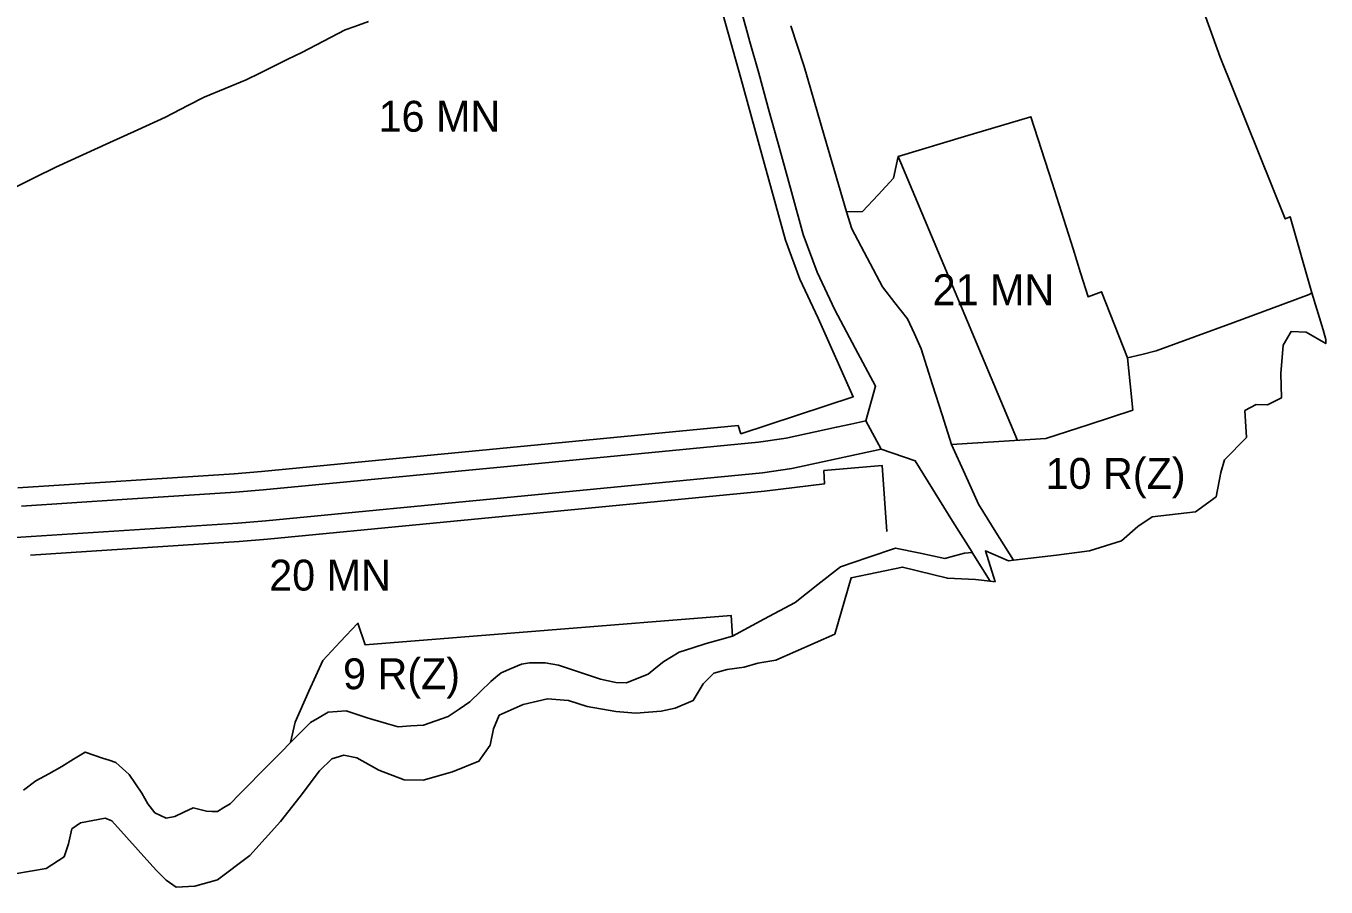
# Model space of a CAD drawing. Extents: x -294445 to -292055, y 21869 to 23693.
# Drawn here: x -292476 to -292055.2, y 22319.6 to 22598.3 of the extents above; entities that cross this region are included whole.
import ezdxf

# ---------------------------------------------------------------- set-up
doc = ezdxf.new("R2010")
doc.units = 0
for name, color, linetype in [('linie_rozgraniczajace', 7, 'Continuous'), ('linie_zabudowy_nieprzekraczalne', 7, 'Continuous'), ('oznaczenia_przeznaczen', 7, 'Continuous')]:
    doc.layers.add(name, color=color, linetype=linetype)

msp = doc.modelspace()

# ---------------------------------------------------------------- linework, layer by layer
at = {"layer": 'linie_rozgraniczajace'}
for points in [[(-292096.57, 22608.04), (-292089.46, 22588.21), (-292068.43, 22535.88), (-292066.8, 22536.58), (-292059.86, 22511.98), (-292060.63, 22511.36), (-292069.128, 22508.23), (-292085.395, 22502.24), (-292110.16, 22493.12), (-292114.84, 22492.01), (-292119.52, 22490.9), (-292123.697, 22501.579), (-292127.875, 22512.259), (-292132.232, 22510.64), (-292134.648, 22518.391), (-292137.063, 22526.143), (-292143.896, 22547.532), (-292150.728, 22568.92), (-292172.208, 22562.503), (-292193.688, 22556.086), (-292195.255, 22549.031), (-292200.228, 22543.666), (-292205.2, 22538.3), (-292210.442, 22538.143), (-292217.625, 22562.805), (-292224.1, 22585.18), (-292228.45, 22598.345)], [(-292244.54, 22603.42), (-292241.69, 22593.21), (-292238.84, 22583), (-292235.435, 22570.67), (-292232.03, 22558.34), (-292228.234, 22544.575), (-292224.439, 22530.811), (-292219.969, 22518.66), (-292214.193, 22506.428), (-292207.612, 22494.063), (-292201.031, 22481.699), (-292204.133, 22470.5), (-292208.978, 22469.445), (-292213.636, 22468.432), (-292229.918, 22464.929), (-292238.876, 22463.599), (-292319.059, 22455.861), (-292399.242, 22448.123), (-292408.21, 22447.394), (-292444.844, 22445.015), (-292477.478, 22442.897)], [(-292228.45, 22598.345), (-292224.1, 22585.18), (-292217.625, 22562.805), (-292210.442, 22538.143), (-292208.74, 22532.64), (-292203.76, 22523.245), (-292198.78, 22513.85), (-292194.745, 22508.675), (-292190.71, 22503.5), (-292188.465, 22498.66), (-292186.22, 22493.82), (-292184.38, 22488.005), (-292182.54, 22482.19), (-292179.47, 22472.495), (-292176.405, 22462.814), (-292172.039, 22453.155), (-292167.677, 22443.511), (-292162.04, 22434.443), (-292156.402, 22425.375), (-292158.03, 22425.18), (-292165.49, 22428.42), (-292162.36, 22418.41), (-292163.963, 22418.597), (-292169.771, 22427.938), (-292169.772, 22427.94), (-292176.066, 22438.065), (-292188.17, 22457.533), (-292199.252, 22461.328), (-292204.133, 22470.5), (-292201.031, 22481.699), (-292207.612, 22494.063), (-292214.193, 22506.428), (-292219.969, 22518.66), (-292224.439, 22530.811), (-292228.234, 22544.575), (-292232.03, 22558.34), (-292235.435, 22570.67), (-292238.84, 22583), (-292241.69, 22593.21), (-292244.54, 22603.42)], [(-292479.86, 22545.93), (-292473.11, 22549.255), (-292466.36, 22552.58), (-292457.6, 22556.565), (-292448.84, 22560.55), (-292439.771, 22564.687), (-292430.8, 22568.78), (-292423.579, 22572.535), (-292418.3, 22575.28), (-292411.525, 22578.075), (-292404.75, 22580.87), (-292400.265, 22583.08), (-292395.78, 22585.29), (-292391.27, 22587.51), (-292386.76, 22589.73), (-292379.72, 22593.38), (-292372.68, 22597.03), (-292369.55, 22598.15), (-292365.19, 22599.78)], [(-292365.19, 22599.78), (-292369.55, 22598.15), (-292372.68, 22597.03), (-292379.72, 22593.38), (-292386.76, 22589.73), (-292391.27, 22587.51), (-292395.78, 22585.29), (-292400.265, 22583.08), (-292404.75, 22580.87), (-292411.525, 22578.075), (-292418.3, 22575.28), (-292423.579, 22572.535), (-292430.8, 22568.78), (-292439.771, 22564.687), (-292448.84, 22560.55), (-292457.6, 22556.565), (-292466.36, 22552.58), (-292473.11, 22549.255)], [(-292473.11, 22549.255), (-292479.86, 22545.93)], [(-292477.478, 22442.897), (-292444.844, 22445.015), (-292408.21, 22447.394), (-292399.242, 22448.123), (-292319.059, 22455.861), (-292238.876, 22463.599), (-292229.918, 22464.929), (-292213.636, 22468.432), (-292208.978, 22469.445), (-292204.133, 22470.5), (-292199.252, 22461.328), (-292228.146, 22455.082), (-292237.661, 22453.67), (-292318.009, 22445.916), (-292398.356, 22438.162), (-292407.48, 22437.42), (-292444.252, 22435.03), (-292481.025, 22432.64)], [(-292481.025, 22432.64), (-292444.252, 22435.03), (-292407.48, 22437.42), (-292398.356, 22438.162), (-292318.009, 22445.916), (-292237.661, 22453.67), (-292228.146, 22455.082), (-292199.252, 22461.328), (-292188.17, 22457.533), (-292176.066, 22438.065), (-292169.772, 22427.94), (-292169.771, 22427.938), (-292172.27, 22427.66), (-292175.46, 22426.82), (-292178.65, 22425.98), (-292186.63, 22427.66), (-292194.61, 22429.34), (-292203.51, 22426.3), (-292212.41, 22423.26), (-292219.75, 22417.5), (-292227.09, 22411.74), (-292237.225, 22406.285), (-292247.36, 22400.83), (-292247.714, 22407.453), (-292306.977, 22402.747), (-292366.24, 22398.04), (-292368.58, 22405.01), (-292374.26, 22398.985), (-292379.94, 22392.96), (-292384.415, 22382.985), (-292388.89, 22373.01), (-292390.42, 22366.36), (-292393.44, 22363.29), (-292396.46, 22360.22), (-292400.15, 22356.475), (-292403.84, 22352.73), (-292406.86, 22349.65), (-292409.88, 22346.57), (-292411.97, 22345.325), (-292414.06, 22344.08), (-292415.81, 22344.11), (-292417.56, 22344.14), (-292421.92, 22345.25), (-292424.86, 22343.87), (-292427.8, 22342.49), (-292430.58, 22341.94), (-292434.29, 22343.59), (-292436.55, 22346.58), (-292438.49, 22350.01), (-292442.55, 22356.05), (-292446.92, 22359.92), (-292449.055, 22360.64), (-292451.19, 22361.36), (-292456.83, 22363.28), (-292460.615, 22360.95), (-292464.4, 22358.62), (-292468.61, 22356.295), (-292472.82, 22353.97), (-292476.825, 22351.01)], [(-292456.83, 22363.28), (-292451.19, 22361.36), (-292449.055, 22360.64), (-292446.92, 22359.92), (-292442.55, 22356.05), (-292438.49, 22350.01), (-292436.55, 22346.58), (-292434.29, 22343.59), (-292430.58, 22341.94), (-292427.8, 22342.49), (-292424.86, 22343.87), (-292421.92, 22345.25), (-292417.56, 22344.14), (-292415.81, 22344.11), (-292414.06, 22344.08), (-292411.97, 22345.325), (-292409.88, 22346.57), (-292406.86, 22349.65), (-292403.84, 22352.73), (-292400.15, 22356.475), (-292396.46, 22360.22), (-292393.44, 22363.29), (-292390.42, 22366.36), (-292383.87, 22372.82), (-292381.055, 22374.495), (-292378.24, 22376.17), (-292375.28, 22376.43), (-292372.32, 22376.69), (-292365.53, 22374.32), (-292359.3, 22372.58), (-292355.49, 22371.47), (-292351.435, 22371.76), (-292347.38, 22372.05), (-292343.34, 22373.415), (-292339.3, 22374.78), (-292335.805, 22377.17), (-292332.31, 22379.56), (-292328.94, 22382.85), (-292325.57, 22386.14), (-292323.905, 22387.55), (-292322.24, 22388.96), (-292318.925, 22390.325), (-292315.61, 22391.69), (-292312.98, 22392.22), (-292310.49, 22392.175), (-292308, 22392.13), (-292303.68, 22391.45), (-292296.89, 22389.165), (-292290.1, 22386.88), (-292287.58, 22386.335), (-292285.06, 22385.79), (-292281.63, 22385.68), (-292278.15, 22387.1), (-292274.67, 22388.52), (-292272.115, 22390.575), (-292269.56, 22392.63), (-292267.05, 22394.11), (-292264.54, 22395.59), (-292260.175, 22397.005), (-292255.81, 22398.42), (-292251.585, 22399.625), (-292247.36, 22400.83), (-292237.225, 22406.285), (-292227.09, 22411.74), (-292219.75, 22417.5), (-292212.41, 22423.26), (-292203.51, 22426.3), (-292194.61, 22429.34), (-292186.63, 22427.66), (-292178.65, 22425.98), (-292175.46, 22426.82), (-292172.27, 22427.66), (-292169.771, 22427.938), (-292163.963, 22418.597), (-292168.63, 22419.14), (-292177.74, 22419.57), (-292192.27, 22423.19), (-292208.94, 22419.73), (-292214.21, 22401.48), (-292233.29, 22393.05), (-292239.13, 22392.11), (-292243.57, 22390.72), (-292249.07, 22389.99), (-292253.34, 22388.86), (-292256.84, 22385.34), (-292260.05, 22379.96), (-292265.84, 22377.47), (-292270.42, 22376.56), (-292278.61, 22375.83), (-292285.1, 22376.43), (-292294.39, 22378.05), (-292300.45, 22379.98), (-292307.22, 22380.51), (-292315.08, 22378.7), (-292322.82, 22375.19), (-292324.73, 22370.8), (-292325.72, 22365.51), (-292329.41, 22360.31), (-292338, 22356.94), (-292347.47, 22354.16)], [(-292347.47, 22354.16), (-292353.59, 22354.3), (-292361.76, 22357.42), (-292368.92, 22361.4), (-292373.16, 22362.34), (-292376.98, 22361.11), (-292380.98, 22357.27), (-292387.29, 22348.93), (-292393.6, 22340.87), (-292403.54, 22329.84), (-292414.03, 22321.91), (-292421.4, 22319.94), (-292427.34, 22319.62), (-292430.59, 22321.81), (-292433.6, 22324.81), (-292434.94, 22326.29), (-292448.23, 22341.01), (-292450.37, 22341.87), (-292458.35, 22340.4), (-292461.18, 22338.4), (-292462.21, 22333.6), (-292463.64, 22329.41), (-292469.43, 22325.63), (-292479.56, 22323.84)], [(-292476.825, 22351.01), (-292472.82, 22353.97), (-292468.61, 22356.295), (-292464.4, 22358.62), (-292460.615, 22360.95), (-292456.83, 22363.28)]]:
    msp.add_lwpolyline(points, dxfattribs=at)
for points in [[(-292210.442, 22538.143), (-292205.2, 22538.3), (-292200.228, 22543.666), (-292195.255, 22549.031), (-292193.688, 22556.086), (-292172.208, 22562.503), (-292150.728, 22568.92), (-292143.896, 22547.532), (-292137.063, 22526.143), (-292134.648, 22518.391), (-292132.232, 22510.64), (-292127.875, 22512.259), (-292123.697, 22501.579), (-292119.52, 22490.9), (-292118.66, 22482.43), (-292117.8, 22473.96), (-292131.855, 22469.365), (-292145.91, 22464.77), (-292161.155, 22463.785), (-292176.405, 22462.814), (-292179.47, 22472.495), (-292182.54, 22482.19), (-292184.38, 22488.005), (-292186.22, 22493.82), (-292188.465, 22498.66), (-292190.71, 22503.5), (-292194.745, 22508.675), (-292198.78, 22513.85), (-292203.76, 22523.245), (-292208.74, 22532.64)], [(-292176.405, 22462.814), (-292161.155, 22463.785), (-292145.91, 22464.77), (-292131.855, 22469.365), (-292117.8, 22473.96), (-292118.66, 22482.43), (-292119.52, 22490.9), (-292114.84, 22492.01), (-292110.16, 22493.12), (-292085.395, 22502.24), (-292069.128, 22508.23), (-292060.63, 22511.36), (-292059.86, 22511.98), (-292056.19, 22500), (-292055.23, 22496.86), (-292055.3, 22495.49), (-292061.68, 22499.21), (-292066.51, 22499.41), (-292069.06, 22495.01), (-292069.87, 22485.86), (-292069.67, 22477.92), (-292074.16, 22475.67), (-292077.86, 22475.83), (-292081.49, 22473.8), (-292081, 22465.13), (-292088.03, 22457.92), (-292089.26, 22453.73), (-292090.78, 22445.95), (-292097.5, 22441.06), (-292111.45, 22439.48), (-292116.17, 22436.29), (-292121.38, 22431.7), (-292131.74, 22428.47), (-292142.43, 22427.05), (-292156.402, 22425.375), (-292162.04, 22434.443), (-292167.677, 22443.511), (-292172.039, 22453.155)], [(-292390.42, 22366.36), (-292388.89, 22373.01), (-292384.415, 22382.985), (-292379.94, 22392.96), (-292374.26, 22398.985), (-292368.58, 22405.01), (-292366.24, 22398.04), (-292306.977, 22402.747), (-292247.714, 22407.453), (-292247.36, 22400.83), (-292251.585, 22399.625), (-292255.81, 22398.42), (-292260.175, 22397.005), (-292264.54, 22395.59), (-292267.05, 22394.11), (-292269.56, 22392.63), (-292272.115, 22390.575), (-292274.67, 22388.52), (-292278.15, 22387.1), (-292281.63, 22385.68), (-292285.06, 22385.79), (-292287.58, 22386.335), (-292290.1, 22386.88), (-292296.89, 22389.165), (-292303.68, 22391.45), (-292308, 22392.13), (-292310.49, 22392.175), (-292312.98, 22392.22), (-292315.61, 22391.69), (-292318.925, 22390.325), (-292322.24, 22388.96), (-292323.905, 22387.55), (-292325.57, 22386.14), (-292328.94, 22382.85), (-292332.31, 22379.56), (-292335.805, 22377.17), (-292339.3, 22374.78), (-292343.34, 22373.415), (-292347.38, 22372.05), (-292351.435, 22371.76), (-292355.49, 22371.47), (-292359.3, 22372.58), (-292365.53, 22374.32), (-292372.32, 22376.69), (-292375.28, 22376.43), (-292378.24, 22376.17), (-292381.055, 22374.495), (-292383.87, 22372.82)]]:
    msp.add_lwpolyline(points, close=True, dxfattribs=at)
at = {"layer": 'linie_zabudowy_nieprzekraczalne'}
for points in [[(-292478.651, 22448.833), (-292408.647, 22453.378), (-292399.773, 22454.1), (-292245.491, 22468.964), (-292244.6, 22466.296), (-292244.6, 22466.296), (-292208.258, 22478.276), (-292219.557, 22503.736), (-292225.508, 22516.339), (-292230.157, 22528.975), (-292237.814, 22556.744), (-292244.621, 22581.395), (-292250.308, 22601.766), (-292257.313, 22625.56), (-292261.649, 22640.762), (-292272.438, 22678.471), (-292275.057, 22688.917), (-292284.695, 22745.774), (-292290.496, 22784.531), (-292295.967, 22812.331)], [(-292193.688, 22556.086), (-292155.073, 22464.178)], [(-292197.392, 22434.73), (-292198.93, 22456.096), (-292217.739, 22454.378), (-292217.537, 22450.135), (-292236.932, 22447.713), (-292397.825, 22432.185), (-292407.042, 22431.436), (-292474.507, 22427.051)]]:
    msp.add_lwpolyline(points, dxfattribs=at)

# ---------------------------------------------------------------- texts
at = {"layer": 'oznaczenia_przeznaczen'}
for s, p in [('16 MN', (-292361.874, 22564.078)), ('21 MN', (-292182.569, 22507.936)), ('10 R(Z)', (-292145.999, 22448.48)), ('20 MN', (-292397.279, 22415.562)), ('9 R(Z)', (-292373.38, 22383.631))]:
    msp.add_text(s, height=10, dxfattribs=at).set_placement(p)

doc.saveas('drawing.dxf')
